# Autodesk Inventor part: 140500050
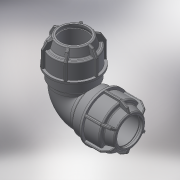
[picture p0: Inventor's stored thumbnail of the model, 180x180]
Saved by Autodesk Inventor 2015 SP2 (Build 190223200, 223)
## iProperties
Created: 2017-08
Part Number: 140500050
Material: Generic
Description: PLASSON L.14 90° ELBOW (SILVER) 50-50
Document SubType Name: Modeling
Designer: KIM
Density: 1 g/cm^3
Appearance: Default
Author: KIM
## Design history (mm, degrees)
derived "140500.ipt"
feature "Solid1::140500.ipt"
tag "TaggingFeature1"
body "Solid1"
other parameters: "d2" = 74, "d4" = 15 deg, "d5" = 48.84, "d6" = 16.1172, "d10" = 92, "d16" = 51, "d17" = 3.7, "d24" = 3.7, "d25" = 82.8, "d26" = 69, "d27" = 3.7, "d28" = 135 deg, "d29" = 2.22, "d31" = 2.5, "d46" = 150 deg, "d49" = 4.6, "d50" = 0, "d58" = 1.5, "d61" = 360 deg, "d63" = 45, "d80" = 72, "d81" = 4, "d84" = 3.7, "d112" = 104, "d113" = 1.04, "d115" = 90 deg, "E_" = 92, "A_" = 104, "l_" = 74
